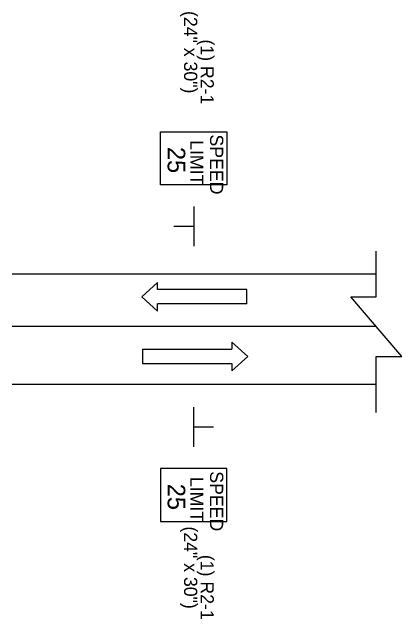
# Model space of a CAD drawing. Extents: x 1368648 to 1927880, y -1037443 to 380209.
# Drawn here: x 1370064 to 1370240.7, y 376158.1 to 376433.4 of the extents above; entities that cross this region are included whole.
import ezdxf

# ---------------------------------------------------------------- set-up
doc = ezdxf.new("R2010")
doc.units = 0
for name, color, linetype in [('Default', 7, 'Continuous'), ('Dimensions', 7, 'Continuous'), ('R_Signs', 7, 'Continuous'), ('R_Signs_Annot', 7, 'Continuous')]:
    doc.layers.add(name, color=color, linetype=linetype)

msp = doc.modelspace()

# ---------------------------------------------------------------- linework, layer by layer
at = {"layer": 'Default'}
for p, q in [((1370146.3, 376345.21), (1370146.3, 376327.16)), ((1370146.3, 376336.18), (1370137.28, 376336.18)), ((1370229.11, 376314.55), (1370063.97, 376314.55)), ((1370229.11, 376290.68), (1370063.97, 376290.68)), ((1370229.11, 376264.44), (1370063.97, 376264.44)), ((1370146.3, 376236.15), (1370146.3, 376254.2)), ((1370146.3, 376245.18), (1370155.33, 376245.18))]:
    msp.add_line(p, q, dxfattribs=at)
msp.add_lwpolyline([(1370229.11, 376251.74), (1370229.11, 376277.14), (1370240.7, 376277.14), (1370217.53, 376304.22), (1370229.11, 376304.22), (1370229.11, 376324.88)], dxfattribs=at)
at = {"layer": 'Dimensions'}
for p, q in [((1370170.41, 376300.97), (1370129.83, 376300.97)), ((1370123.09, 376280.39), (1370163.67, 376280.39))]:
    msp.add_line(p, q, dxfattribs=at)
for points in [[(1370170.41, 376300.97), (1370170.41, 376307.47), (1370129.83, 376307.47), (1370129.83, 376310.72), (1370122.71, 376304.22), (1370129.83, 376297.72), (1370129.83, 376300.97)], [(1370123.09, 376280.39), (1370123.09, 376273.9), (1370163.67, 376273.9), (1370163.67, 376270.65), (1370170.79, 376277.14), (1370163.67, 376283.64), (1370163.67, 376280.39)]]:
    msp.add_lwpolyline(points, dxfattribs=at)
at = {"layer": 'R_Signs'}
for points in [[(1370131.3, 376355.08), (1370131.3, 376379.08), (1370161.3, 376379.08), (1370161.3, 376355.08)], [(1370131.3, 376226.28), (1370131.3, 376202.28), (1370161.3, 376202.28), (1370161.3, 376226.28)]]:
    msp.add_lwpolyline(points, close=True, dxfattribs=at)

# ---------------------------------------------------------------- texts
for s, height, p in [('SPEED', 6, (1370153.71, 376377.84)), ('LIMIT', 6, (1370144.71, 376375.28)), ('25', 8, (1370134.48, 376372.21)), ('SPEED', 6, (1370153.71, 376225.06)), ('LIMIT', 6, (1370144.71, 376222.5)), ('25', 8, (1370134.48, 376219.41))]:
    msp.add_text(s, height=height, rotation=270, dxfattribs=at).set_placement(p)
at = {"layer": 'R_Signs_Annot'}
for s, p in [('(24" x 30")', (1370141.92, 376433.85)), ('(1) R2-1', (1370149.43, 376420.95)), ('(24" x 30")', (1370141.92, 376200.05)), ('(1) R2-1', (1370149.43, 376187.15))]:
    msp.add_text(s, height=6, rotation=270, dxfattribs=at).set_placement(p)

doc.saveas('drawing.dxf')
